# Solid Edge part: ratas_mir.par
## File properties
Author: Argu
Template: Iso Part.par
Last saved by: Argu
Revision: 3
Application: Solid Edge
Accuracy: 0,990
Username: Argu
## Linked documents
ratas.par
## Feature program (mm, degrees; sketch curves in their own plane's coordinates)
part copy "CopiedPart_1"
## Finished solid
Body 1: solid body, 120 faces, 196 edges, 78 vertices, 3 separate solids.
  Faces by surface: torus 49, plane 25, cylinder 24, blend 14, cone 5, sphere 2, spline 1
  Edges by curve: circle 105, line 58, intersection 29, ellipse 4
Bounding box of the edges (mm; curved faces can reach further): 28.000 x 55.178 x 36.907, from (-14, -33.2388, -11.9933) to (14, 21.939, 24.9132).
Cylindrical faces by radius (mm): R1 x4, R2 x9, R3 x2, R4 x2, R5 x5, R11.7933 x2
Conical faces (half-angle, radius in mm at the cone's reference point): 89.808 deg R0 x1, 89.8303 deg R8.4756 x2, 89.9002 deg R6.3482 x2
Toroidal faces (ring radius, tube radius in mm): R2.014 r5.9533 x2, R2.9536 r3.2766 x2, R3 r1 x4, R4.3572 r1 x1, R4.8474 r1 x1, R6 r1 x2, R6.0893 r1 x1, R6.0897 r1 x1, R6.5687 r0.5 x2, R6.5781 r0.5 x2, R6.5794 r1 x1, R8.9995 r3.0995 x2, R8.9995 r3.6 x2, R9 r3 x14, R10.4368 r0.2 x4, R11.2225 r0.2 x4, R11.7613 r0.2 x4
Spherical faces by radius (mm): R2 x2
Planar faces by outward normal: +x 6, +y 2, +z 3, -x 7, -y 2, -z 3, oblique 2
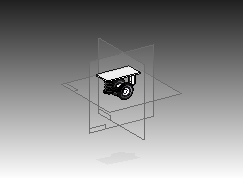
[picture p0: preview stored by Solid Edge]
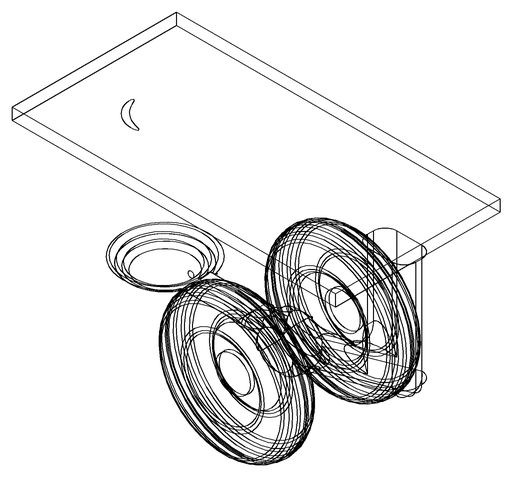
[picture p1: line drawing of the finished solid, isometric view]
